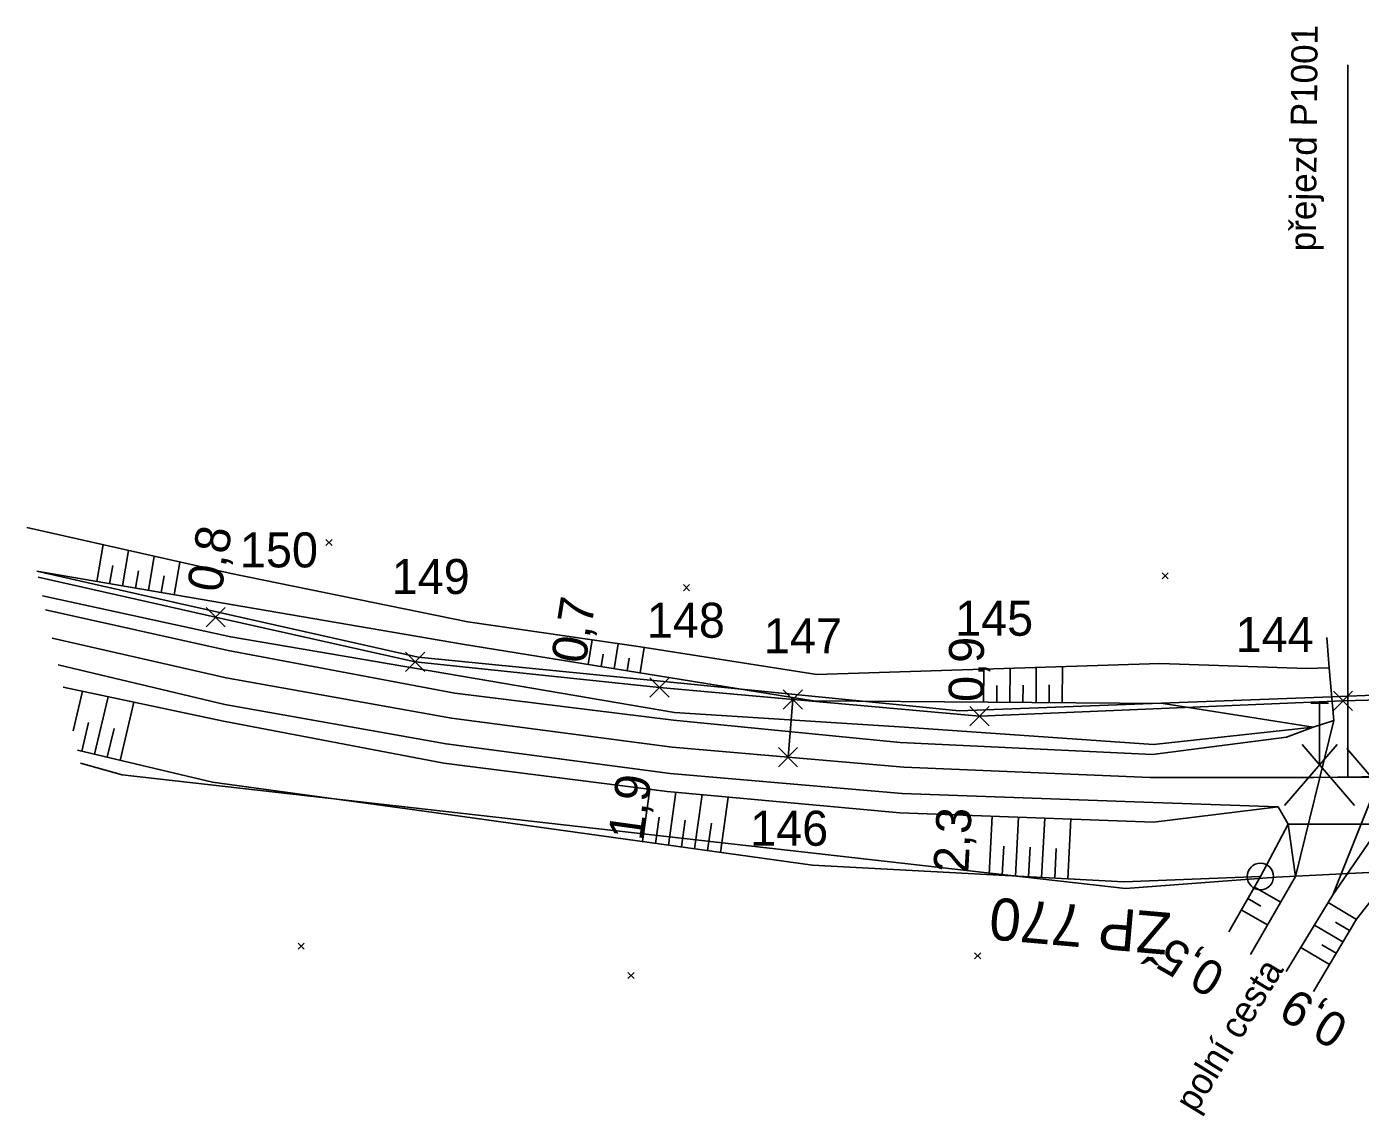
# Model space of a CAD drawing. Extents: x -805730 to -804640, y -1150889 to -1150366.
# Drawn here: x -805497.5 to -805421.3, y -1150709.2 to -1150646.9 of the extents above; entities that cross this region are included whole.
import ezdxf

# ---------------------------------------------------------------- set-up
doc = ezdxf.new("R2010")
doc.units = 0
for name, color, linetype in [('0381KM032-037P - Vrstva 1', 7, 'Continuous'), ('0381KM032-037P - Vrstva 19', 7, 'Continuous'), ('0381KM032-037P - Vrstva 4', 7, 'Continuous'), ('0381KM032-037P - Vrstva 48', 7, 'Continuous'), ('0381KM032-037P - Vrstva 49', 7, 'Continuous'), ('0381KM032-037P - Vrstva 51', 7, 'Continuous'), ('Default', 7, 'Continuous'), ('hran DP - hran DP', 7, 'Continuous'), ('PSR_C2_2_Lomove_body_Vimperk - Vrstva 60', 7, 'Continuous'), ('PSR_C2_2_trasa_Vimperk - Kabelová trasa', 7, 'Continuous'), ('vyt_sit - stávající', 7, 'Continuous')]:
    doc.layers.add(name, color=color, linetype=linetype)

msp = doc.modelspace()

# ---------------------------------------------------------------- linework, layer by layer
at = {"layer": '0381KM032-037P - Vrstva 1'}
msp.add_lwpolyline([(-805364.564, -1150682.932), (-805366.036, -1150683.288), (-805378.364, -1150685.708), (-805390.905, -1150687.547), (-805419.964, -1150689.775), (-805423.956, -1150689.798), (-805433.29, -1150689.8), (-805447.38, -1150689.21), (-805460.61, -1150688.07), (-805473.24, -1150686.41), (-805486.12, -1150684.11), (-805496.07, -1150681.84)], dxfattribs=at)
at = {"layer": '0381KM032-037P - Vrstva 19'}
msp.add_line((-805425.408, -1150692.468), (-805420.073, -1150692.467), dxfattribs=at)
at = {"layer": '0381KM032-037P - Vrstva 4'}
for p, q in [((-805421.995, -1150689.771), (-805421.995, -1150649.075)), ((-805423.106, -1150685.551), (-805424.106, -1150685.551)), ((-805423.606, -1150685.551), (-805423.606, -1150689.051)), ((-805422.606, -1150687.901), (-805425.606, -1150691.401)), ((-805421.606, -1150691.401), (-805424.606, -1150687.901)), ((-805422.051, -1150688.145), (-805419.051, -1150691.645)), ((-805423.956, -1150689.798), (-805419.82, -1150689.74))]:
    msp.add_line(p, q, dxfattribs=at)
for points in [[(-805485.852, -1150681.76), (-805496.622, -1150679.425)], [(-805423.968, -1150686.92), (-805425.507, -1150687.489), (-805433.167, -1150688.486), (-805447.577, -1150687.793), (-805460.544, -1150686.523), (-805473.033, -1150684.969), (-805486.003, -1150682.535), (-805496.44, -1150680.221)], [(-805423.968, -1150686.92), (-805433.105, -1150687.911), (-805447.337, -1150686.911), (-805460.493, -1150686.088), (-805485.852, -1150681.76)], [(-805425.977, -1150691.468), (-805433.128, -1150691.222), (-805447.474, -1150690.705), (-805460.736, -1150689.572), (-805473.542, -1150687.873), (-805486.195, -1150685.623), (-805495.723, -1150683.361)], [(-805425.408, -1150692.468), (-805425.977, -1150691.468), (-805433.111, -1150692.346), (-805447.611, -1150691.816), (-805460.898, -1150690.591), (-805473.672, -1150688.976), (-805486.257, -1150686.575), (-805495.432, -1150684.633)]]:
    msp.add_lwpolyline(points, dxfattribs=at)
at = {"layer": '0381KM032-037P - Vrstva 48'}
for p, q in [((-805493.516, -1150678.599), (-805493.154, -1150676.492)), ((-805492.038, -1150678.853), (-805491.689, -1150676.823)), ((-805492.777, -1150678.726), (-805492.599, -1150677.692)), ((-805490.56, -1150679.107), (-805490.224, -1150677.155)), ((-805489.082, -1150679.361), (-805488.759, -1150677.486)), ((-805491.299, -1150678.98), (-805491.128, -1150677.985)), ((-805489.821, -1150679.234), (-805489.656, -1150678.277)), ((-805465.411, -1150683.343), (-805465.185, -1150681.938)), ((-805463.93, -1150683.582), (-805463.701, -1150682.155)), ((-805462.45, -1150683.82), (-805462.217, -1150682.374)), ((-805464.671, -1150683.462), (-805464.557, -1150682.754)), ((-805463.19, -1150683.701), (-805463.074, -1150682.982)), ((-805442.816, -1150685.486), (-805442.802, -1150683.603)), ((-805441.316, -1150685.497), (-805441.302, -1150683.554)), ((-805439.816, -1150685.508), (-805439.801, -1150683.505)), ((-805438.316, -1150685.519), (-805438.301, -1150683.457)), ((-805442.066, -1150685.491), (-805442.059, -1150684.535)), ((-805440.566, -1150685.502), (-805440.559, -1150684.516)), ((-805439.066, -1150685.514), (-805439.059, -1150684.497)), ((-805494.863, -1150687.121), (-805494.328, -1150684.869)), ((-805493.641, -1150688.469), (-805492.86, -1150685.181)), ((-805492.182, -1150688.816), (-805491.392, -1150685.492)), ((-805494.371, -1150688.296), (-805493.982, -1150686.66)), ((-805492.911, -1150688.642), (-805492.519, -1150686.989)), ((-805462.306, -1150693.457), (-805461.892, -1150690.465)), ((-805460.82, -1150693.663), (-805460.401, -1150690.636)), ((-805459.334, -1150693.868), (-805458.906, -1150690.775)), ((-805457.848, -1150694.074), (-805457.411, -1150690.913)), ((-805461.563, -1150693.56), (-805461.355, -1150692.059)), ((-805460.077, -1150693.766), (-805459.865, -1150692.235)), ((-805442.496, -1150695.345), (-805442.316, -1150692.013)), ((-805440.998, -1150695.425), (-805440.817, -1150692.068)), ((-805439.5, -1150695.506), (-805439.318, -1150692.123)), ((-805438.003, -1150695.587), (-805437.819, -1150692.178)), ((-805458.591, -1150693.971), (-805458.375, -1150692.407)), ((-805441.747, -1150695.385), (-805441.657, -1150693.713)), ((-805440.249, -1150695.466), (-805440.158, -1150693.781)), ((-805438.751, -1150695.546), (-805438.66, -1150693.848)), ((-805427.337, -1150696.056), (-805425.831, -1150696.919)), ((-805427.71, -1150696.707), (-805426.958, -1150697.138)), ((-805428.083, -1150697.358), (-805426.58, -1150698.219)), ((-805421.505, -1150697.899), (-805423.112, -1150696.945)), ((-805422.272, -1150699.189), (-805423.895, -1150698.224)), ((-805421.889, -1150698.544), (-805422.696, -1150698.064)), ((-805423.038, -1150700.478), (-805424.678, -1150699.504)), ((-805422.655, -1150699.834), (-805423.471, -1150699.349))]:
    msp.add_line(p, q, dxfattribs=at)
at = {"layer": '0381KM032-037P - Vrstva 49'}
for p, q in [((-805480.059, -1150676.544), (-805480.413, -1150676.19)), ((-805480.059, -1150676.19), (-805480.413, -1150676.544)), ((-805432.255, -1150678.453), (-805432.609, -1150678.099)), ((-805432.255, -1150678.099), (-805432.609, -1150678.453)), ((-805459.618, -1150679.124), (-805459.972, -1150678.77)), ((-805459.618, -1150678.77), (-805459.972, -1150679.124)), ((-805426.992, -1150695.453), (-805425.408, -1150692.468)), ((-805481.651, -1150699.609), (-805482.005, -1150699.255)), ((-805481.651, -1150699.255), (-805482.005, -1150699.609)), ((-805442.98, -1150700.163), (-805443.334, -1150699.809)), ((-805442.98, -1150699.809), (-805443.334, -1150700.163)), ((-805462.79, -1150701.281), (-805463.144, -1150700.927)), ((-805462.79, -1150700.927), (-805463.144, -1150701.281))]:
    msp.add_line(p, q, dxfattribs=at)
for points in [[(-805424.361, -1150683.566), (-805432.744, -1150683.276), (-805452.346, -1150683.913), (-805462.434, -1150682.34), (-805472.303, -1150680.897), (-805485.837, -1150678.147), (-805497.518, -1150675.505)], [(-805422.802, -1150686.532), (-805423.968, -1150686.92), (-805432.545, -1150685.563), (-805452.563, -1150685.412), (-805472.604, -1150682.185), (-805485.723, -1150679.939), (-805496.946, -1150678.009)], [(-805423.968, -1150686.92), (-805433.105, -1150687.911), (-805447.337, -1150686.911), (-805460.493, -1150686.088), (-805485.852, -1150681.76), (-805496.622, -1150679.425)], [(-805422.802, -1150686.532), (-805423.053, -1150683.538), (-805424.361, -1150683.566)], [(-805425.408, -1150692.468), (-805425.977, -1150691.468), (-805433.111, -1150692.346), (-805447.611, -1150691.816), (-805460.898, -1150690.591), (-805473.672, -1150688.976), (-805486.257, -1150686.575), (-805495.432, -1150684.633)], [(-805428.796, -1150698.607), (-805426.992, -1150695.453), (-805434.791, -1150695.763), (-805452.595, -1150694.797), (-805474.791, -1150691.727), (-805486.897, -1150690.069), (-805494.608, -1150688.237)], [(-805427.559, -1150699.915), (-805424.986, -1150695.461), (-805425.408, -1150692.468)], [(-805420.073, -1150692.467), (-805422.844, -1150696.501), (-805425.524, -1150700.881)], [(-805423.96, -1150702.025), (-805421.499, -1150697.887), (-805419.738, -1150695.668)]]:
    msp.add_lwpolyline(points, dxfattribs=at)
at = {"layer": '0381KM032-037P - Vrstva 51'}
for points in [[(-805425.524, -1150700.881), (-805422.844, -1150696.501), (-805419.834, -1150688.974), (-805419.997, -1150686.968), (-805420.48, -1150681.602)], [(-805422.802, -1150686.532), (-805423.053, -1150683.538), (-805423.2, -1150681.793)], [(-805422.802, -1150686.532), (-805424.986, -1150695.461), (-805427.559, -1150699.915)]]:
    msp.add_lwpolyline(points, dxfattribs=at)
at = {"layer": 'hran DP - hran DP'}
for p, q in [((-805496.945, -1150678.011), (-805488.96, -1150679.81)), ((-805488.96, -1150679.81), (-805475.13, -1150682.93)), ((-805475.13, -1150682.93), (-805447.24, -1150685.68)), ((-805433.7, -1150685.59), (-805423.42, -1150685.2)), ((-805423.42, -1150685.2), (-805418.81, -1150685.03)), ((-805447.24, -1150685.68), (-805444.22, -1150685.98)), ((-805444.22, -1150685.98), (-805433.7, -1150685.59)), ((-805492.06, -1150689.65), (-805494.44, -1150688.972)), ((-805434.71, -1150696.14), (-805492.06, -1150689.65)), ((-805420.42, -1150695.2), (-805426.08, -1150695.49)), ((-805426.08, -1150695.49), (-805434.71, -1150696.14))]:
    msp.add_line(p, q, dxfattribs=at)
at = {"layer": 'PSR_C2_2_Lomove_body_Vimperk - Vrstva 60'}
for p, q in [((-805487.265, -1150681.179), (-805486.165, -1150680.079)), ((-805486.165, -1150681.179), (-805487.265, -1150680.079)), ((-805475.86, -1150683.732), (-805474.76, -1150682.632)), ((-805474.76, -1150683.732), (-805475.86, -1150682.632)), ((-805461.896, -1150685.2), (-805460.796, -1150684.1)), ((-805460.796, -1150685.2), (-805461.896, -1150684.1)), ((-805454.273, -1150685.883), (-805453.173, -1150684.783)), ((-805453.173, -1150685.883), (-805454.273, -1150684.783)), ((-805422.82, -1150685.965), (-805421.72, -1150684.865)), ((-805421.72, -1150685.965), (-805422.82, -1150684.865)), ((-805443.601, -1150686.84), (-805442.501, -1150685.74)), ((-805442.501, -1150686.84), (-805443.601, -1150685.74)), ((-805454.545, -1150689.19), (-805453.445, -1150688.09)), ((-805453.445, -1150689.19), (-805454.545, -1150688.09))]:
    msp.add_line(p, q, dxfattribs=at)
at = {"layer": 'PSR_C2_2_trasa_Vimperk - Kabelová trasa'}
msp.add_line((-805453.995, -1150688.64), (-805453.723, -1150685.333), dxfattribs=at)
for points in [[(-805496.866, -1150678.357), (-805486.715, -1150680.629), (-805475.31, -1150683.182), (-805461.346, -1150684.65), (-805443.051, -1150686.29), (-805422.27, -1150685.415)], [(-805422.27, -1150685.415), (-805395.913, -1150684.713), (-805381.013, -1150683.039), (-805372.216, -1150682.032)]]:
    msp.add_lwpolyline(points, dxfattribs=at)
at = {"layer": 'vyt_sit - stávající'}
msp.add_line((-805427.042, -1150695.453), (-805426.942, -1150695.453), dxfattribs=at)
msp.add_circle((-805426.992, -1150695.453), 0.756, dxfattribs=at)

# ---------------------------------------------------------------- texts
at = {"layer": '0381KM032-037P - Vrstva 4'}
msp.add_text('přejezd P1001', height=1.5, rotation=89.45469, dxfattribs=at).set_placement((-805423.832, -1150659.74))
at = {"layer": '0381KM032-037P - Vrstva 48'}
for s, rotation, p in [('0,8', 80.24135, (-805486.401, -1150679.289)), ('0,7', 80.85275, (-805465.576, -1150683.349)), ('0,9', 89.56781, (-805442.816, -1150685.486)), ('1,9', 82.1252, (-805462.306, -1150693.457)), ('2,3', 86.89432, (-805443.693, -1150695.28)), ('0,5', 150.22776, (-805428.88, -1150700.694)), ('0,9', 149.25871, (-805421.832, -1150703.661))]:
    msp.add_text(s, height=2, rotation=rotation, dxfattribs=at).set_placement(p)
at = {"layer": '0381KM032-037P - Vrstva 51'}
msp.add_text('polní cesta', height=1.5, rotation=58.5387, dxfattribs=at).set_placement((-805430.69, -1150709.032))
at = {"layer": 'Default'}
for s, p in [('150', (-805485.328, -1150677.792)), ('149', (-805476.651, -1150679.313)), ('148', (-805462.067, -1150681.812)), ('145', (-805444.443, -1150681.698)), ('147', (-805455.373, -1150682.693)), ('144', (-805428.406, -1150682.629)), ('146', (-805456.161, -1150693.696))]:
    msp.add_text(s, height=2, dxfattribs=at).set_placement(p)
at = {"layer": 'vyt_sit - stávající'}
msp.add_text('ŽP 770', height=2.4, rotation=175, dxfattribs=at).set_placement((-805432.049, -1150697.54))

doc.saveas('drawing.dxf')
